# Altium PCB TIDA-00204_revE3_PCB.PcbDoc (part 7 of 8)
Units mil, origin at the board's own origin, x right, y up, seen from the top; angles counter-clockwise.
Board outline 4600 x 3740 mil, 8 copper layers (TopLayer - S1 (.GTL), MidLayer1 - S2 (.G1), MidLayer2 - S3 (.G2), MidLayer3 - S4 (.G3), MidLayer4 - S5 (.G4), MidLayer5 - S6 (.G5), MidLayer6 - S7 (.G6), BottomLayer - S8 (.GBL)), stack 58.938 mil thick; 536 components, 354 nets, 2015 pads, 1067 vias.
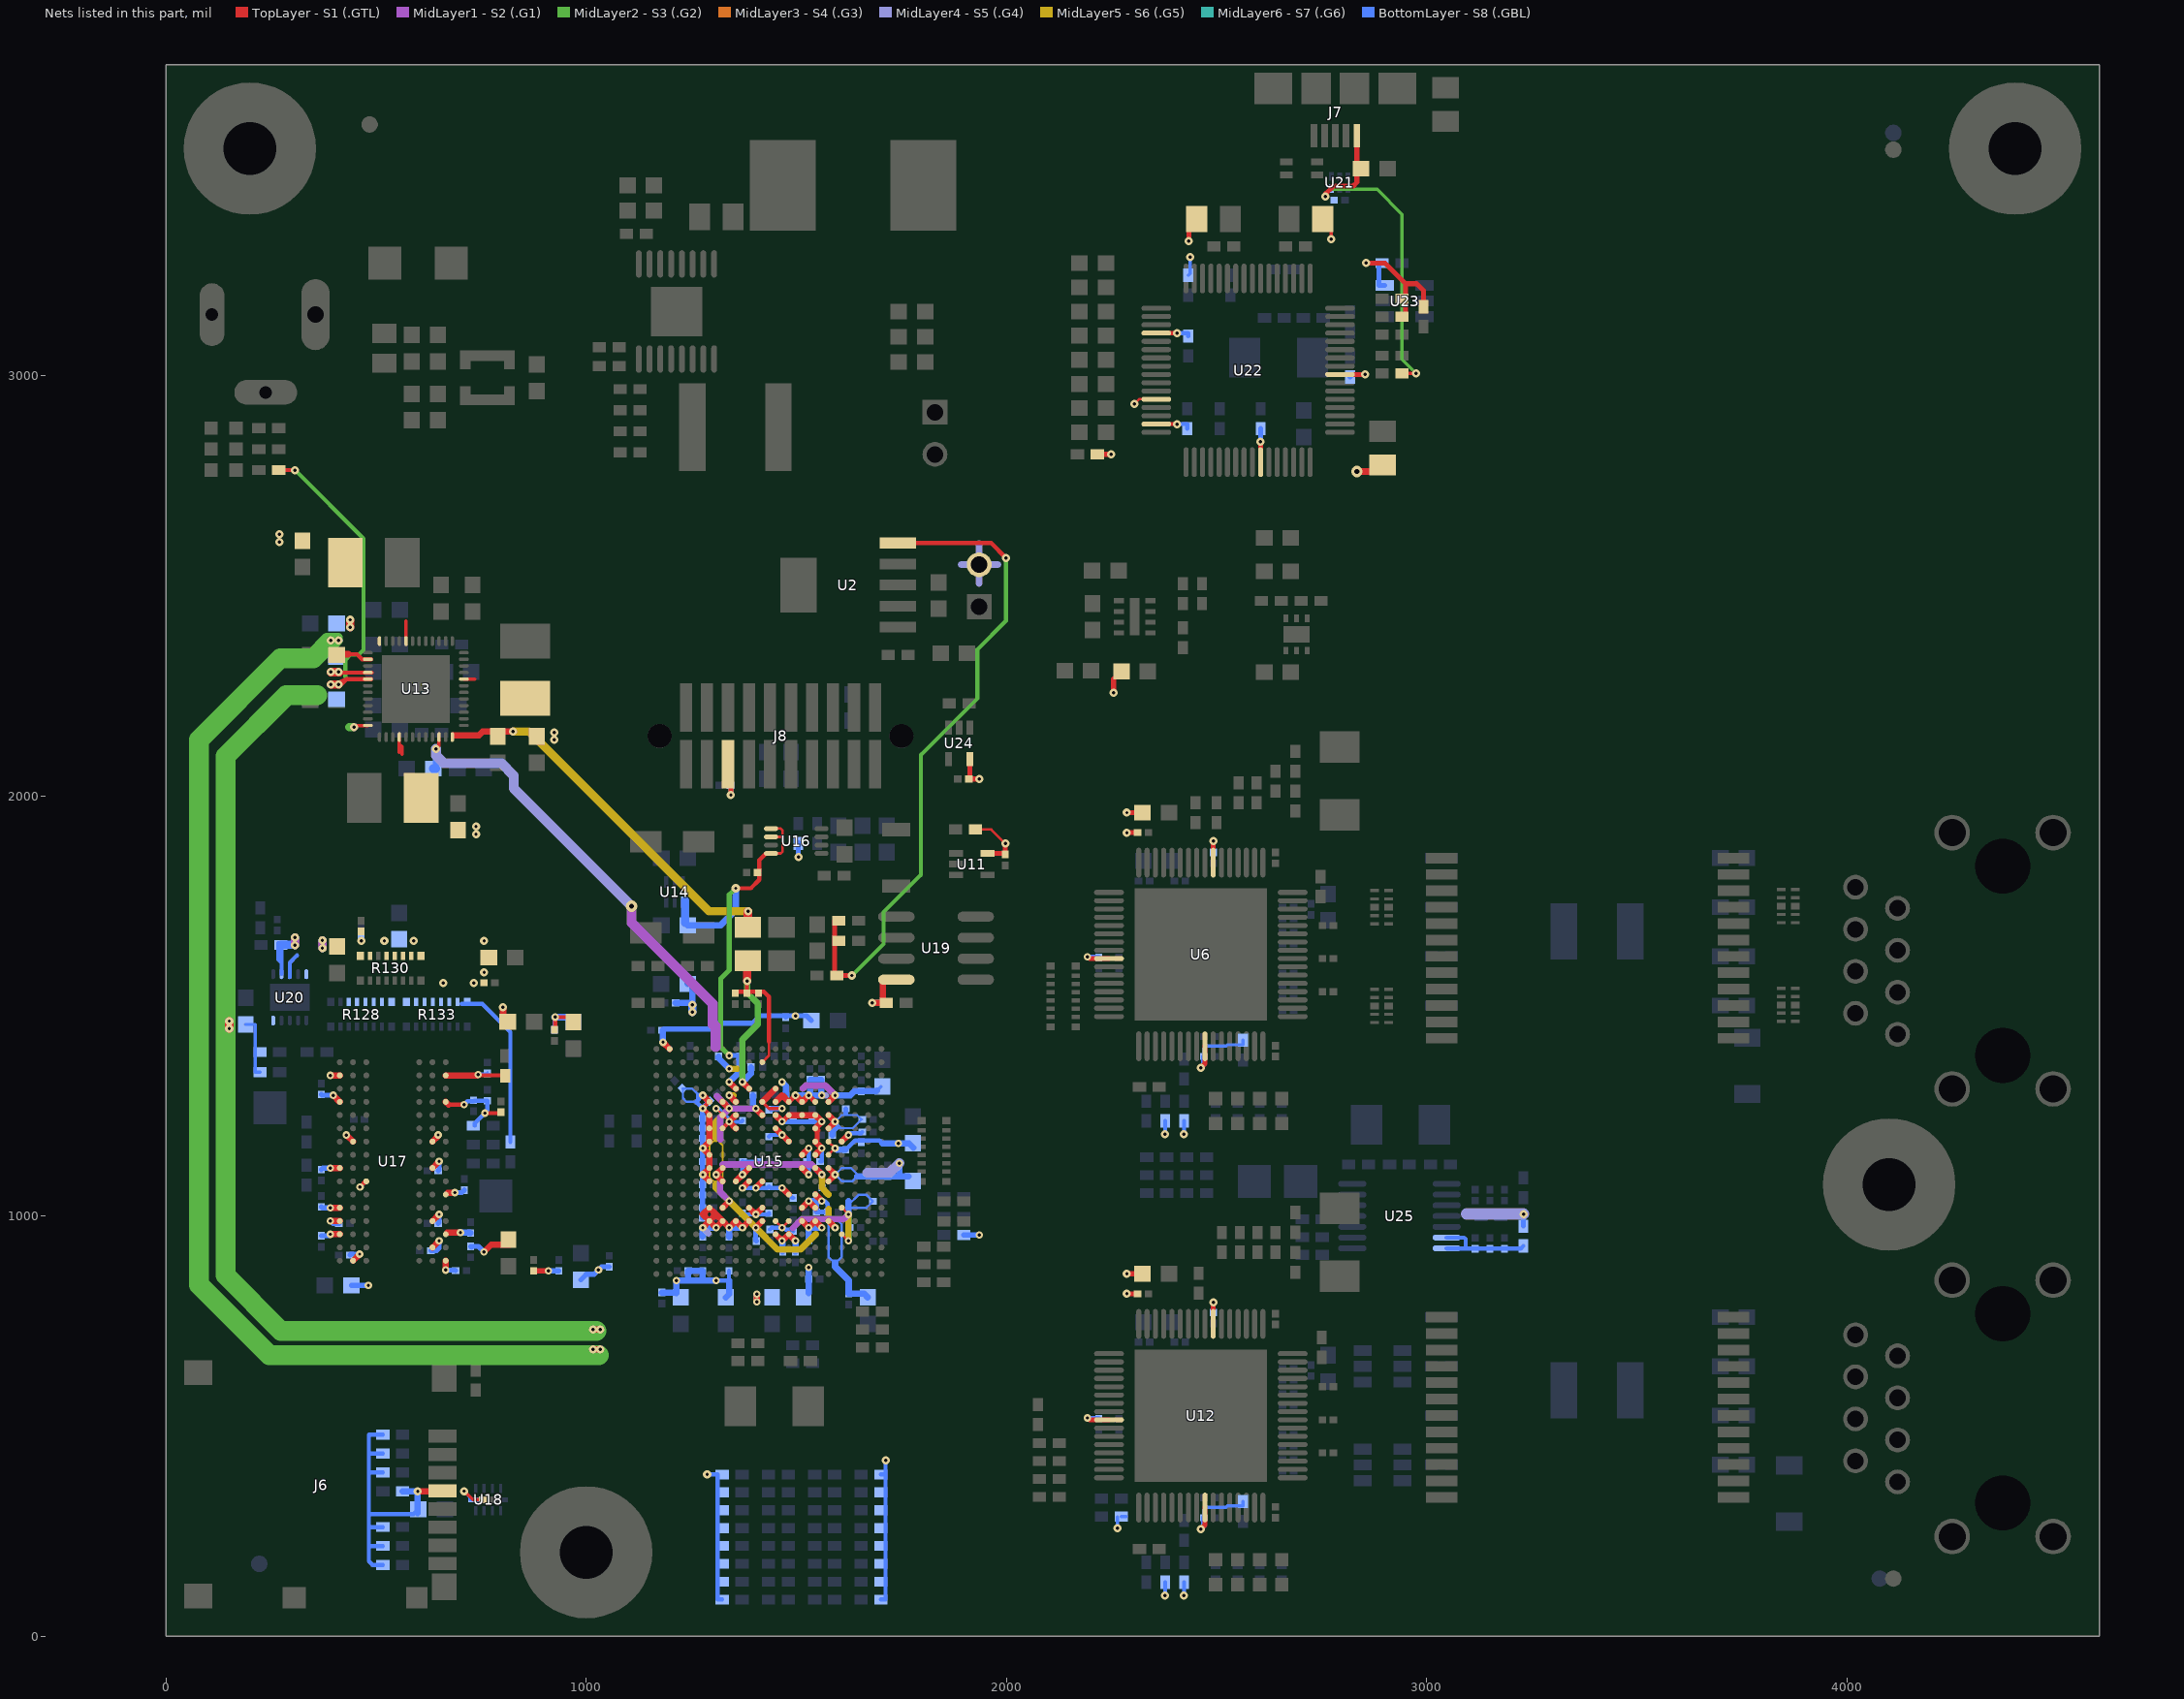
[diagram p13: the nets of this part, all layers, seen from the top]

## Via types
v1: diameter 19.68, hole 7.87, TopLayer - S1 (.GTL) to BottomLayer - S8 (.GBL), 600 vias
v2: diameter 17.72, hole 7.87, TopLayer - S1 (.GTL) to BottomLayer - S8 (.GBL), 408 vias
v3: diameter 27.56, hole 11.81, TopLayer - S1 (.GTL) to BottomLayer - S8 (.GBL), 31 vias
v4: diameter 20, hole 7.87, TopLayer - S1 (.GTL) to BottomLayer - S8 (.GBL), tented both sides, 11 vias
v5: diameter 15.75, hole 7.87, TopLayer - S1 (.GTL) to BottomLayer - S8 (.GBL), 9 vias
v6: diameter 20, hole 7.87, TopLayer - S1 (.GTL) to BottomLayer - S8 (.GBL), 5 vias
v7: diameter 15, hole 7.87, TopLayer - S1 (.GTL) to BottomLayer - S8 (.GBL), 2 vias
v8: diameter 18, hole 7.87, TopLayer - S1 (.GTL) to BottomLayer - S8 (.GBL), 1 vias

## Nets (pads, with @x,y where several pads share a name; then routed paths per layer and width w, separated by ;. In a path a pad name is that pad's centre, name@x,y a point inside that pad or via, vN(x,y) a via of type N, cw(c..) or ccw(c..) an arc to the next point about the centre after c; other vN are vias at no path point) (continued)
VAUX2: C96.1 C102.1 C103.1 C104.1 C108.1 C109.1 C110.1 C114.1 C115.1 C116.1 C117.2 C118.2 C119.2 C120.2 C121.2 C122.2 C123.2 C124.2 C125.2 C126.2 R70.2 R83.2 R84.2 R85.2 R86.2 R87.2 R88.2 R89.2 R90.2 R91.2 R92.2 R93.2 R94.2 R95.2 R96.2 R97.2 R98.2 R117.2 R118.2 U2.5 U13.48 U15.E10 U15.E11 U15.E12 U15.E13 U15.F14 U15.G14 U15.K14 U15.L14 U15.N5 U15.P5 U15.P6 U15.P7 U15.P8 U15.P12 U15.P13 | length 4215
  TopLayer - S1 (.GTL) w9.84: U2.5@1741.61,2601.5 1963.46,2601.5 v1(1999.02,2565.94)
  TopLayer - S1 (.GTL) w12: U15.E11@1482.24,1271.76 v2(1497.99,1287.48) ; v2(1529.49,1287.48) U15.E13@1545.24,1271.75 ; R118.2@1601.38,1702.5 1591.5,1702.5 1591.5,1572.5 R70.2@1596.12,1572.5 v1(1632.5,1572.5)
  TopLayer - S1 (.GTL) w15: v2(1277.52,972.52) U15.P5@1293.27,988.27 ; 1277.52,1004.04 U15.P5@1293.25,988.31 ; 1277.53,1004.04 U15.N5@1293.27,1019.76 1309.02,1004.03 ; U15.P5@1293.27,988.27 1309.02,1004.03 ; v2(1309.02,972.52) U15.P6@1324.76,988.27 1309.02,1004.03 ; v2@1309,972.56 U15.P5@1293.27,988.27 ; U15.P6@1324.76,988.27 v2(1340.51,972.52) U15.P7@1356.26,988.27 v2(1372.01,972.52) U15.P8@1387.76,988.27 ; U15.E10@1450.75,1271.73 1466.5,1287.49 ; 1466.54,1287.52 1466.5,1287.49 ; U15.E11@1482.24,1271.75 1466.5,1287.49 ; v2(1497.99,1287.48) U15.E12@1513.74,1271.78 ; U15.P12@1513.75,988.28 v2(1529.49,972.52) U15.P13@1545.24,988.27 ; U15.E12@1513.74,1271.75 v2(1529.49,1287.48) ; U15.P13@1545.24,988.27 v2(1560.98,972.52) ; U15.L14@1576.73,1082.76 v2(1592.48,1098.5) U15.K14@1576.73,1114.25 ; U15.G14@1576.73,1208.76 v2(1592.48,1224.49) ; U15.F14@1576.73,1240.24 v2(1592.48,1224.49)
  TopLayer - S1 (.GTL) w19.68: v1(438.98,2400.83) v1@438.98,2415.83
  MidLayer2 - S3 (.G2) w9.84: v1(1632.5,1572.5) 1707.68,1647.68 1707.68,1723.43 1796.26,1812.01 1796.26,2097.44 1931.1,2232.28 1931.1,2348.43 1999.02,2416.34 v1(1999.02,2565.94)
  MidLayer4 - S5 (.G4) w15: v2(1277.52,972.52) 1291.04,959 ; v2(1560.98,1287.48) 1571.52,1287.48
  MidLayer4 - S5 (.G4) w23.62: 1669.25,1103.35 1722.44,1103.35 v2(1745.08,1125.98)
  BottomLayer - S8 (.GBL) w5: 1592.48,1208.82 1592.66,1209 1607.97,1209 ; C121.2@1657.01,1230 C121.2@1655,1230 ; 1607.97,1209 1634,1209 C121.2@1655,1230 ; 1607.97,1209 v2(1592.48,1224.49) 1607.99,1240 1645,1240 C121.2@1655,1230
  BottomLayer - S8 (.GBL) w5.51: v2(1592.48,1098.5) 1608.15,1114.17 1630.32,1114.17 1649.98,1094.51 1651.66,1092.82 ; v2@1593.5,1098.43 1609.25,1082.68 1632.48,1082.68 1644.31,1094.51
  BottomLayer - S8 (.GBL) w6: C124.2@1529.49,1324.51 C124.2@1532.5,1324.51 ; v2(1560.98,1287.48) v2@1562.5,1287.48
  BottomLayer - S8 (.GBL) w10: v1(1288,385) 1312.5,385 1312.5,87.5 R98.2@1323.88,87.5 ; v2(1309.02,846.54) 1339.36,846.54 1339.43,846.47 1339.49,846.54 1340,847.05 C118.2@1340,869.51 ; R97.2@1701.12,87.5 1712.5,87.5 R83.2@1712.5,385 ; R83.2@1701.12,385 R83.2@1712.5,385 ; v1(1712.5,419) R83.2@1712.5,385
  BottomLayer - S8 (.GBL) w12: 1617.99,1243.49 C123.2@1617.99,1255
  BottomLayer - S8 (.GBL) w15: C119.2@1180,817.99 1213.5,817.99 1214.53,816.97 v2(1214.53,846.54) 1242.99,846.54 ; C117.2@1277.5,950.98 v2(1277.52,972.52) v2(1309.02,972.52) ; v2(1309.02,846.54) 1277.5,846.54 ; C104.1@1332.5,806.5 1340.51,814.51 1340.51,846.54 1339.49,846.54 1339.36,846.54 ; C102.1@1340,950.49 1340.51,951 v2(1340.51,972.52) v2(1372.01,972.52) ; v2(1497.99,1287.48) v2(1529.49,1287.48) v2@1532.5,1287.48 ; C110.1@1529.47,817.02 v2(1529.47,878.04) ; C108.1@1530,942.99 1530,972.01 v2(1529.49,972.52) v2(1560.98,972.52) ; v2(1560.98,1287.48) v2@1560,1287.48 ; C122.2@1585.49,1192.5 1585.49,1201.83 1592.48,1208.82 v2(1592.48,1224.49) ; 1644.31,1094.51 1649.98,1094.51 C114.1@1685,1094.51 C115.1@1717.5,1094.51 1745.08,1094.51 ; 1242.99,846.54 1277.5,846.54 ; 1242.99,846.54 C120.2@1242.99,870 1277.01,870 C103.1@1277.5,869.51 1277.5,846.54 ; v2@1532.5,1287.48 C124.2@1532.5,1324.51 C125.2@1560,1324.51 v2@1560,1287.48 ; v2@1532.5,1287.48 v2@1560,1287.48
  BottomLayer - S8 (.GBL) w15.75: v2(1745.08,1125.98) 1745.08,1094.51 C116.1@1767.17,1094.51
  other v1: 438.98,2418.83
VAUX33: C93.1 C136.1 C137.1 C233.1 R66.2 R135.2 R137.2 U13.4 U13.12 U15.N15 U15.R15 U20.10 | length 4020.4
  TopLayer - S1 (.GTL) w6: U15.R15@1608.23,956.77 v2(1623.98,941.02) ; U15.N15@1608.23,1019.76 v2(1623.98,1004.02)
  TopLayer - S1 (.GTL) w8: v1(448,2163) 452.39,2167.39 U13.12@480.83,2167.39
  TopLayer - S1 (.GTL) w9: v1@389,2291 391,2289 415.26,2289 v1@419.63,2293.37 ; v1@414,2299 v1@419.63,2293.37 ; v1@416.63,2293.37 v1@419.63,2293.37 ; U13.4@490,2293.37 U13.4@480.83,2293.37 v1@419.63,2293.37
  TopLayer - S1 (.GTL) w9.84: R66.2@268.62,2775 v1(307.5,2775)
  TopLayer - S1 (.GTL) w15.75: v1(1016,730) v1(1034,730)
  TopLayer - S1 (.GTL) w19.68: v1(151,1446) v1(151,1464) ; v1(393,2294.5) v1(411,2294.5)
  MidLayer1 - S2 (.G1) w15: 1491.25,971.25 1513.11,993.11 1613.07,993.11 v2(1623.98,1004.02)
  MidLayer1 - S2 (.G1) w19.68: v1(151,1446) v1(151,1464)
  MidLayer2 - S3 (.G2) w9.84: v1(307.5,2775) 470.47,2612.03 470.47,2347.44 458.66,2335.63 438.98,2335.63 427.17,2323.82 427.17,2282.48
  MidLayer2 - S3 (.G2) w19.68: 436.5,2163 v1(448,2163)
  MidLayer2 - S3 (.G2) w47.24: 360,2239 287,2239 142,2094 142,859 274,727 v1@1025,727
  MidLayer3 - S4 (.G3) w19.68: v1(151,1446) v1(151,1464)
  MidLayer4 - S5 (.G4) w19.68: v1(151,1446) v1(151,1464)
  MidLayer5 - S6 (.G5) w15: v2(1623.98,941.02) v2(1623.98,1004.02)
  MidLayer5 - S6 (.G5) w19.68: v1(151,1446) v1(151,1464)
  MidLayer6 - S7 (.G6) w19.68: v1(151,1446) v1(151,1464)
  BottomLayer - S8 (.GBL) w5: 1623.98,1020 1624.28,1019.7
  BottomLayer - S8 (.GBL) w5.51: 1622.83,1025.2 1623.98,1026.34 1648.74,1051.1 1665.91,1051.1 C136.1@1682.01,1035 1666.71,1019.7 1624.28,1019.7
  BottomLayer - S8 (.GBL) w8: C233.1@190,1456 213,1456 213,1342.5 R137.2@223.88,1342.5
  BottomLayer - S8 (.GBL) w15: v2(1623.98,941.02) v2(1623.98,1004.02) 1623.98,1020 1623.98,1026.34 1623.98,1035.28
VDAC: C98.1 C127.1 C128.1 C129.1 C130.1 C131.1 U13.22 U15.E6 U15.E14 U15.F9 U15.K13 U15.N6 U15.P9 U15.P14 | length 2843.4
  TopLayer - S1 (.GTL) w8: v1(643,2112) 650.12,2119.12 U13.22@650.12,2139.83
  TopLayer - S1 (.GTL) w15: U15.N6@1324.76,1019.76 v2(1340.51,1035.51) ; U15.E6@1324.76,1271.73 v2(1340.51,1255.98) ; v2(1403.5,972.52) U15.P9@1419.25,988.29 ; v2(1403.5,1255.98) U15.F9@1419.25,1240.26 ; U15.K13@1545.24,1114.25 v2(1560.98,1098.5) ; U15.P14@1576.73,988.27 v2(1592.48,972.52) ; U15.E14@1576.73,1271.75 v2(1592.48,1287.48)
  MidLayer1 - S2 (.G1) w15: 1318.9,1079.72 1318.9,1057.13 v2(1340.51,1035.51)
  MidLayer1 - S2 (.G1) w15.75: 1311.02,1285.47 v2(1340.51,1255.98) ; 1318.9,1182.09 1318.9,1234.37 v2(1340.51,1255.98) ; 1324.8,1123.03 1536.46,1123.03 v2(1560.98,1098.5) ; v2(1403.5,1255.98) v2(1340.51,1255.98) ; 1515.75,1304.13 1522.64,1311.02 1568.94,1311.02 v2(1592.48,1287.48)
  MidLayer1 - S2 (.G1) w23.62: v3(1108.27,1737.2) 1108.27,1697.73 1301.18,1504.82 1301.18,1454.72 ; 1308.07,1401.57 1308.07,1451.77
  MidLayer4 - S5 (.G4) w23.62: v1(643,2112) 643,2096.17 661.42,2077.76 798.23,2077.76 827.76,2048.23 827.76,2017.72 v3(1108.27,1737.2)
  MidLayer5 - S6 (.G5) w4.72: 1293.31,1092.48 1293.31,1168.35 1309.02,1184.06 1324.8,1168.27 1324.8,1092.56 1309.02,1076.77 1293.31,1092.48
  MidLayer5 - S6 (.G5) w15: 1576.77,1016.73 1576.77,988.23 v2(1592.48,972.52)
  MidLayer5 - S6 (.G5) w15.75: 1309.02,1076.77 1309.02,1067.01 v2(1340.51,1035.51) v2(1403.5,972.52) 1455.75,920.28 1509.84,920.28 1546.26,956.69 ; 1309.02,1184.06 1309.02,1224.49 v2(1340.51,1255.98) ; v2(1560.98,1098.5) 1560.98,1066.97 1576.77,1051.18
  BottomLayer - S8 (.GBL) w6: C129.1@1560.98,1068.71 v2(1560.98,1098.5)
  BottomLayer - S8 (.GBL) w8: C131.1@1691.88,1298.38 C131.1@1701,1307.5
  BottomLayer - S8 (.GBL) w12: v2(1403.5,972.52) 1403.5,941.99 C130.1@1405,940.49
  BottomLayer - S8 (.GBL) w15: C98.1@643,2065 v1(643,2112) ; C127.1@1397.01,1287.5 1397.01,1262.48 v2(1403.5,1255.98) ; v2(1592.48,1287.48) 1628.62,1287.48 1638.15,1297.01 C128.1@1655,1297.01 1690.51,1297.01 C131.1@1691.88,1298.38
  BottomLayer - S8 (.GBL) w20: C98.1@636.5,2065 C98.1@643,2065
VDC_USB: C234.1 C235.1 J7.1 R155.2 U21.6 | length 831.5
  TopLayer - S1 (.GTL) w7.87: R155.2@2941.12,3005 v1(2974.41,3005)
  TopLayer - S1 (.GTL) w11.81: v1@2759.84,3433.07 2777.56,3450.79 2824.8,3450.79 2833.68,3459.67 J7.1@2833.68,3570.71
  MidLayer2 - S3 (.G2) w7.87: v1@2759.84,3433.07 2769.68,3442.91 2881.89,3442.91 2940.94,3383.86 2940.94,3038.46 v1(2974.41,3005)
  other v1: 2758.86,3426.18
VDD1_SMPS: C86.1 C185.1 C186.1 C187.1 C188.1 C189.1 C190.1 L3.2 U13.32 U15.A2 U15.F10 U15.F11 U15.F12 U15.F13 U15.G13 U15.H13 U15.J13 | length 818.1
  TopLayer - S1 (.GTL) w8: U13.32@709.17,2277.62 734.62,2277.62
  TopLayer - S1 (.GTL) w12: v2(1466.5,1224.49) U15.F11@1482.23,1240.26 ; U15.H13@1545.24,1177.26 1550,1182.02 U15.G13@1550,1204
  TopLayer - S1 (.GTL) w15: v2(1183.03,1413.46) U15.A2@1198.78,1397.72 ; U15.F10@1450.76,1240.25 v2(1466.5,1224.49) ; U15.F11@1482.23,1240.26 1545.24,1240.26 v2(1560.98,1224.49) 1545.24,1208.76 U15.G13@1550,1204 ; U15.J13@1545.24,1145.77 v2(1560.98,1161.5) U15.H13@1545.25,1177.25
  BottomLayer - S8 (.GBL) w9.84: C190.1@1557.01,1130 1560.98,1130 v2(1560.98,1161.5)
  BottomLayer - S8 (.GBL) w11.81: v2(1466.5,1224.49) v2(1560.98,1224.49)
  BottomLayer - S8 (.GBL) w12: C187.1@1180.49,1442.5 1183.03,1442.5 1185.41,1444.88 1302.38,1444.88 1316.16,1458.66 1395.67,1458.66 1413.46,1476.46 C186.1@1478.46,1476.46 ; C186.1@1475,1472.99 C186.1@1478.46,1476.46 ; C185.1@1536,1465 1524.55,1476.46 v2(1497.99,1476.46) C186.1@1478.46,1476.46
  BottomLayer - S8 (.GBL) w15: v2(1183.03,1413.46) C187.1@1183.03,1442.5
  other v1: 924,2133 924,2151
VDD2_SMPS: C88.1 C170.1 C171.1 C172.1 C173.1 C174.1 C175.1 C176.1 C177.1 C178.1 C179.1 C180.1 C181.1 C182.1 C183.1 C184.1 L4.2 U13.44 U15.F6 U15.F7 U15.G6 U15.G7 U15.G10 U15.H11 U15.J12 U15.K6 U15.K8 U15.K12 U15.L6 U15.L7 U15.L8 U15.L9 U15.M11 U15.M13 U15.N8 U15.N9 U15.N12 U15.N13 | length 1613.3
  TopLayer - S1 (.GTL) w4: U15.F6@1324.76,1240.26 U15.F6@1324.76,1241.24
  TopLayer - S1 (.GTL) w5: v2@1309,1257 U15.F6@1324.76,1241.24 ; U15.F6@1324.76,1240.26 v2(1340.51,1224.49)
  TopLayer - S1 (.GTL) w8: U13.44@571.38,2368.17 571.38,2416.12
  TopLayer - S1 (.GTL) w10: U15.G6@1324.76,1208.78 v2(1340.51,1224.49)
  TopLayer - S1 (.GTL) w15: U15.L6@1324.76,1082.76 v2(1309.02,1098.5) U15.K6@1324.75,1114.27 ; U15.L7@1356.26,1082.76 v2(1372.01,1098.5) ; U15.G7@1356.26,1208.76 v2(1340.51,1224.49) U15.F7@1356.24,1240.25 ; v2(1372.01,1067.01) U15.L8@1387.76,1082.76 ; v2(1372.01,1098.5) U15.K8@1387.75,1114.26 ; U15.N8@1387.76,1019.76 v2(1403.5,1004.02) U15.N9@1419.25,1019.78 ; v2(1403.5,1067.01) U15.L9@1419.25,1082.78 ; U15.G10@1450.75,1208.75 U15.H11@1482.24,1177.26 ; v2(1466.5,1067.01) U15.M11@1482.24,1051.26 ; U15.N12@1513.74,1019.76 v2(1529.49,1035.51) ; U15.K12@1513.74,1114.25 v2(1529.49,1098.5) ; U15.J12@1513.74,1145.77 v2(1529.49,1161.5) ; v2(1529.49,1035.51) U15.N13@1545.24,1019.76 ; U15.M13@1545.24,1051.26 v2(1560.98,1035.51)
  BottomLayer - S8 (.GBL) w4.92: 1606.69,865.75 1608.27,867.32
  BottomLayer - S8 (.GBL) w5.51: 1588.88,883.56 1592.72,887.4 1608.07,902.76 1608.07,980.31 1598.03,990.35 1576.57,990.35 1576.57,902.76 1585.63,893.7 1597.83,893.7
  BottomLayer - S8 (.GBL) w7.87: C184.1@1372.01,1129.02 C184.1@1372.99,1130 C181.1@1409.51,1130
  BottomLayer - S8 (.GBL) w9.84: v2(1309.02,1255.98) 1313.9,1255.98 1340.51,1229.37 v2(1340.51,1224.49) 1369.23,1224.49 C182.1@1372,1227.26 ; C175.1@1372,1006.76 1372,1004.02 v2(1403.5,1004.02) 1435,1004.02 C180.1@1435,1007.01 ; v2(1372.01,1067.01) v2(1403.5,1067.01) 1431,1067.01 C183.1@1435,1071.01 1439,1067.01 v2(1466.5,1067.01) 1490.51,1042.99 C172.1@1492.5,1042.99 ; C176.1@1435,1188.99 1439,1192.99 v2(1466.5,1192.99) ; v2(1529.49,1098.5) v2(1529.49,1161.5) ; v2(1560.98,1035.51) 1567.83,1035.51 1574.51,1028.84 C173.1@1574.51,1010
  BottomLayer - S8 (.GBL) w11.81: v2(1372.01,1098.5) C184.1@1372.01,1129.02 ; 1547.99,1036.65 1547.99,1035.51 C174.1@1547.99,1010 C173.1@1574.51,1010 1576.57,1007.93 1576.57,990.35
  BottomLayer - S8 (.GBL) w15: v2(1529.49,1035.51) 1547.99,1035.51 v2(1560.98,1035.51)
  BottomLayer - S8 (.GBL) w15.75: C179.1@1212.99,1507.5 v1@1252.95,1507.5 ; C171.1@1241.5,1552.5 1252.95,1552.5 v1@1252.95,1507.5 ; v1(1252.95,1502.95) v1@1252.95,1507.5 ; 1592.72,888.39 1592.72,887.4 1592.72,879.72 1606.69,865.75 1625,847.44 C178.1@1625,815.49 1661,815.49 C170.1@1670,806.5
  BottomLayer - S8 (.GBL) w19.68: v1(1252.95,1484.95) v1(1252.95,1502.95)
  other v1: 270,2604 270,2622
VDDA_ADC: C144.1 C195.1 C196.1 C197.1 L6.1 U15.B9 U15.D8 | length 647.8
  TopLayer - S1 (.GTL) w6.3: U15.B9@1419.25,1366.24 1435,1381.99 1435,1415.02
  TopLayer - S1 (.GTL) w10: C195.1@1355,1530.49 1358.51,1534 C196.1@1382.5,1534 ; C196.1@1382.5,1530.49 C196.1@1382.5,1534 ; v1(1383,1559) 1382.5,1558.5 C196.1@1382.5,1534 ; 1435,1415.02 1435,1522 1423,1534 C196.1@1382.5,1534
  TopLayer - S1 (.GTL) w15: v2(1372.01,1318.98) U15.D8@1387.76,1303.25
  TopLayer - S1 (.GTL) w20: v1(1383,1559) L6.1@1383,1597
  MidLayer2 - S3 (.G2) w15: v2(1372.01,1318.98) 1372.01,1420.01 1409,1457 1409,1505.5 1383,1531.5 v1(1383,1559)
  BottomLayer - S8 (.GBL) w15: v2(1372.01,1318.98) 1392.5,1339.47 C144.1@1392.5,1354.51
VDDIO: C35.1 C40.1 C41.1 C42.1 C43.1 C44.1 C67.1 C68.1 C69.1 C70.1 C71.1 C207.2 C238.2 C239.2 C243.2 C244.2 C245.2 C246.2 C247.2 J3.2 J8.5 L9.1 L11.1 L12.1 L14.1 R12.1 R28.1 R29.1 R30.2 R38.2 R49.2 R55.1 R56.1 R59.2 R76.2 R146.2 R148.2 R149.2 R150.2 R152.2 R156.2 U6.23 U6.41 U6.57 U11.5 U12.23 U12.41 U12.57 U19.8 U22.20 U22.28 U22.31 U22.42 U22.56 U23.6 U24.5 | length 3010.1
  TopLayer - S1 (.GTL) w5.91: R38.2@1926.12,1920 1963.78,1920 v1(1997.5,1886.28) ; v1(2304.13,2932.09) 2315.65,2943.6 U22.28@2356.5,2943.6
  TopLayer - S1 (.GTL) w7.87: L9.1@2752.5,3372.5 2772.64,3352.36 v1(2772.64,3324.8)
  TopLayer - S1 (.GTL) w9.84: U22.31@2356.5,2884.55 v1(2405.51,2884.55) ; U22.20@2356.5,3101.08 v1(2405.51,3101.08)
  TopLayer - S1 (.GTL) w11.81: v1(1344.39,2002.26) J8.5@1344.39,2075 ; C243.2@1910.49,2040 C243.2@1913.09,2040 ; U24.5@1913.09,2087.6 C243.2@1913.09,2040 ; v1(1935.04,2040) C243.2@1913.09,2040 ; U11.5@1954.9,1863.09 1994.9,1863.09 C35.1@1997.5,1860.49 v1(1997.5,1886.28) ; R146.2@2216.12,2812.5 v1(2249.02,2812.5) ; v1(2434.06,3319.88) 2434.06,3354.06 L11.1@2452.5,3372.5 ; U22.42@2604.53,2794 v1(2604.53,2842.72) ; U22.56@2793.5,3002.66 v1(2853.64,3002.66) ; v1(2855.32,3267.72) 2900.59,3267.72 2949.8,3218.5 ; R149.2@2941.12,3140 2949.8,3140 2949.8,3218.5 ; R150.2@2992.5,3163.62 2992.5,3202.38 2976.38,3218.5 2949.8,3218.5
  TopLayer - S1 (.GTL) w12: v2@2197.44,515.16 U12.41@2244,515.16 ; v2@2197.44,1612.66 U6.41@2244,1612.66 ; v1(2255,2245) 2255,2277.5 R12.1@2273.5,2296 ; v1(2286.5,815) C68.1@2312.01,815 ; v1(2286.5,862.5) C67.1@2323.5,862.5 ; v1(2286.5,1912.5) C41.1@2312.01,1912.5 ; v1(2286.5,1960) C40.1@2323.5,1960 ; v1(2462.5,255) 2472.34,264.84 U12.57@2472.34,306.5 ; v1(2462.5,1352.5) 2472.34,1362.34 U6.57@2472.34,1404 ; U12.23@2492.03,743.5 v1(2492,795) ; U6.23@2492.03,1841 v1(2492,1892.5)
  TopLayer - S1 (.GTL) w15: v1(1680.5,1507.5) 1705.5,1507.5 1705.5,1562.5 U19.8@1738.01,1562.5
  TopLayer - S1 (.GTL) w15.75: v3(2833.66,2771.65) 2895,2771.65 L12.1@2895,2787.5
  MidLayer4 - S5 (.G4) w15.75: v1(1680.5,1507.5) 1715.18,1507.5 ; 1892.52,2550 J3.2@1935,2550 ; 1935,2504.96 J3.2@1935,2550 ; 1935,2600.35 J3.2@1935,2550 ; 1979.53,2550 J3.2@1935,2550
  MidLayer4 - S5 (.G4) w27.56: 3095,1005 v1(3230,1005)
  BottomLayer - S8 (.GBL) w7.87: v1(2263.78,257.45) R49.2@2263.78,284.45 ; R49.2@2273.62,285 R49.2@2284.45,285 ; R156.2@2432.5,3238.62 2437.01,3243.13 v1(2437.01,3281.5) ; C71.1@2469.51,282.5 2469.51,300.16 2476.38,307.03 2522.64,307.03 2525.59,309.98 2562.5,309.98 R55.1@2562.5,321.12 ; C44.1@2469.51,1380 2469.51,1397.66 2476.38,1404.53 2522.64,1404.53 2525.59,1407.48 2562.5,1407.48 R29.1@2562.5,1418.62
  BottomLayer - S8 (.GBL) w9.84: v1(2405.51,2884.55) 2430,2884.55 C245.2@2430,2873.88 ; v1(2405.51,3101.08) 2432.5,3101.08 C244.2@2432.5,3093.62
  BottomLayer - S8 (.GBL) w10: v1(2377.5,97) R56.1@2377.5,128.88 ; v1(2377.5,1194.5) R28.1@2377.5,1226.38 ; v1(2422.5,97) R59.2@2422.5,128.88 ; v1(2422.5,1194.5) R30.2@2422.5,1226.38
  BottomLayer - S8 (.GBL) w11.81: C238.2@1342.99,2025 1344.39,2023.6 v1(1344.39,2002.26) ; v1(1504.92,1854.33) 1504.92,1888.8 R152.2@1505,1888.88 ; R76.2@1898.62,955 v2(1935.5,955) ; v1(2604.53,2842.72) 2604.53,2873.88 C246.2@2605,2873.88 ; C247.2@2817.5,2996.38 2823.78,3002.66 v1(2853.64,3002.66) ; v1(2855.32,3267.72) 2885.83,3267.72 2885.83,3214.9 U23.6@2900.26,3214.9 ; L14.1@3230,976.12 v1(3230,1005)
  BottomLayer - S8 (.GBL) w12: v2@2199.51,517.99 C70.1@2220,517.99 ; v2@2199.51,1615.49 C43.1@2220,1615.49 ; v1(2462.5,255) 2469.51,262.01 C71.1@2469.51,282.5 ; v1(2462.5,1352.5) 2469.51,1359.51 C44.1@2469.51,1380 ; C69.1@2492,770.36 v1(2492,795) ; C42.1@2492,1867.86 v1(2492,1892.5)
  other v2: 2192.91,519.68 2192.91,1617.18
VDDIO_CDC: C255.1 C256.1 C257.1 L14.2 U25.6 U25.7 | length 255.1
  BottomLayer - S8 (.GBL) w9.84: U25.7@3047.2,923.23 3047.93,922.5 3092.5,922.5 ; U25.6@3047.2,948.82 3088.68,948.82 3092.5,945 3092.5,922.5 ; L14.2@3230,928.88 3223.62,922.5 3092.5,922.5
VDDS_DDR: C90.1 C148.1 C149.1 C150.1 C151.1 C152.1 C153.1 C154.1 C155.1 C156.1 C157.1 C158.1 C159.1 C160.1 C161.1 C162.1 C163.1 C164.1 C165.1 C166.1 C167.1 C168.1 C169.1 C204.2 C211.1 C212.1 C213.1 C214.1 C215.1 C216.1 C217.1 C218.1 C219.1 C220.1 C221.1 C222.1 C223.1 C224.1 C231.1 C232.1 L5.2 R129.2 R136.2 U13.16 U15.E5 U15.F5 U15.G5 U15.H5 U15.J5 U15.K5 U15.L5 U17.A1 U17.A8 U17.B2 U17.C1 U17.C9 U17.D2 U17.D9 U17.E9 U17.F1 U17.G7 U17.H2 U17.H9 U17.K2 U17.K8 U17.N1 U17.N9 U17.R1 U17.R9 U20.2 | length 2656.4
  TopLayer - S1 (.GTL) w8: 555.63,2103.37 555.63,2123.37 ; U13.16@555.63,2139.83 555.63,2123.37 ; 562,2099 562,2117 555.63,2123.37
  TopLayer - S1 (.GTL) w9.84: v2@740.99,1334.72 806.66,1334.72 R129.2@807.5,1333.88
  TopLayer - S1 (.GTL) w10: v2@462.48,1069.48 475.76,1082.76 U17.G7@477.01,1082.76 ; v2@648,1190.75 v2(648,1193) ; U17.C1@665.98,956.77 U17.C1@669.88,960.67 ; U17.F1@665.98,1051.26 U17.F1@670.57,1055.85 ; 672.75,1264.96 v2(709.73,1264.96) ; v2(759.39,1245) 795.49,1245 C166.1@797.5,1247.01 ; C168.1@925,1442.99 926.18,1442.99 v2(926.18,1473.43) 957.5,1473.43 C232.1@957.5,1461.5 ; U15.E5@1292.25,1271.75 1277.5,1257 U15.F5@1293.27,1241.23
  TopLayer - S1 (.GTL) w12: C161.1@875,869.51 v2(910.01,869.51)
  TopLayer - S1 (.GTL) w15: v2(391.76,956.77) U17.C9@414.02,956.77 ; v2(391.76,988.27) U17.D9@414.02,988.27 ; v2(391.76,1019.76) U17.E9@414.02,1019.76 ; v2(391.76,1114.25) U17.H9@414.02,1114.25 ; v2(391.76,1334.72) U17.R9@414.02,1334.72 ; v2(398.28,1287.47) U17.N9@414.02,1271.73 ; v2(429.76,1192.99) U17.K8@445.51,1177.24 ; U17.A8@445.51,893.78 v2(461.26,909.53) ; v2(462.19,1069.48) v2@462.48,1069.48 ; U17.B2@634.49,925.28 v2(650.24,941.03) ; U17.D2@634.49,988.27 v2(650.24,1004.02) ; U17.H2@634.49,1114.25 v2(650.24,1130) ; U17.K2@634.49,1177.24 v2@648,1190.75 ; v2(665.98,871.51) U17.A1@665.98,893.78 ; U17.N1@665.98,1271.73 672.75,1264.96 ; U17.R1@665.98,1334.72 v2@740.99,1334.72 ; U17.C1@669.88,960.67 v2(701.04,960.67) ; U17.F1@670.57,1055.85 v2(687.57,1055.85) ; v2(756.9,914.9) 774,932 C231.1@818.5,932 ; v2(1277.52,1098.5) U15.L5@1293.27,1082.76 ; v2(1277.52,1098.5) U15.K5@1293.27,1114.25 ; v2(1277.52,1287.48) 1293.27,1271.75 U15.E5@1292.25,1271.75 ; U15.K5@1293.27,1114.25 1293.26,1145.78 v2(1277.52,1161.5) 1293.26,1177.25 U15.F5@1293.27,1241.23
  TopLayer - S1 (.GTL) w15.75: v1(802.17,1497.05) 802.17,1462.5 C211.1@813.5,1462.5
  MidLayer1 - S2 (.G1) w19.68: v1(307,1645) v1(307,1663)
  MidLayer2 - S3 (.G2) w19.68: v1(307,1645) v1(307,1663)
  MidLayer3 - S4 (.G3) w19.68: v1(307,1645) v1(307,1663)
  MidLayer5 - S6 (.G5) w19.68: v1(307,1645) v1(307,1663)
  MidLayer6 - S7 (.G6) w19.68: v1(307,1645) v1(307,1663)
  BottomLayer - S8 (.GBL) w5: C165.1@759.42,1336.67 C165.1@765.47,1342.72 ; C158.1@1229.19,1303.31 C158.1@1230.32,1302.18 ; 1262.04,1271.46 1262.04,1271.85 ; v2@1274.06,1290.94 v2(1277.52,1287.48)
  BottomLayer - S8 (.GBL) w5.51: C158.1@1229.19,1303.31 1252.2,1303.31 1264.57,1290.94 ; C158.1@1230.32,1302.18 1230.32,1280.51 1238.98,1271.85 1262.04,1271.85 ; 1264.57,1275.98 1264.57,1286.22 ; v2@1274.06,1290.94 1264.57,1290.94 ; v2(1277.52,1287.48) 1276.26,1286.22 1264.57,1286.22 ; 1264.57,1286.22 1264.57,1290.94
  BottomLayer - S8 (.GBL) w8: R136.2@275.31,1643.31 R136.2@273.62,1645 v1(307,1645) v1@307,1645.58
  BottomLayer - S8 (.GBL) w9.06: R136.2@267.72,1649.61 267.72,1610.24 275.31,1602.64 ; U20.2@275.31,1575.62 275.31,1602.64 ; R136.2@275.31,1643.31 275.31,1602.64
  BottomLayer - S8 (.GBL) w9.84: 1262.04,1271.46 v2(1277.52,1255.98) ; 1262.04,1272 v2@1276.26,1286.22
  BottomLayer - S8 (.GBL) w10: v2(709.73,1264.96) 717.77,1273 732.25,1273 733.76,1274.51 C160.1@765,1274.51 765,1250.61 v2(759.39,1245) 735,1220.61 C204.2@735,1215 ; v2(742.94,1336.67) C165.1@759.42,1336.67 ; C162.1@925,1442.99 v2@925,1473.43
  BottomLayer - S8 (.GBL) w12: C215.1@370,952.99 387.98,952.99 v2(391.76,956.77) ; C217.1@370,1022.01 372.25,1019.76 v2(391.76,1019.76) ; C224.1@370,1110.49 373.76,1114.25 v2(391.76,1114.25) ; C216.1@370,1289.51 372.04,1287.47 v2(398.28,1287.47) ; v2(391.76,988.27) 397.53,982.5 C222.1@412.01,982.5 ; C223.1@437.99,907.5 440.02,909.53 v2(461.26,909.53) ; C212.1@441.5,835 v2(482,835) ; C219.1@630.49,917.5 643.9,917.5 650.24,923.84 v2(650.24,941.03) ; C213.1@647.99,982.5 650.24,984.75 v2(650.24,1004.02) ; C220.1@647.99,1107.5 650.24,1109.75 v2(650.24,1130) ; v2(665.98,871.51) 688,871.51 C218.1@689.51,870 ; v2(687.57,1055.85) 703.84,1055.85 C221.1@710,1062.01 ; C164.1@727.69,925.3 C164.1@725,927.99 743.81,927.99 v2(756.9,914.9) ; v2(910.01,869.51) C167.1@935,869.51 ; C148.1@987.5,848.5 1000.5,861.5 1019,861.5 v2(1029.5,872) 1037.01,879.51 C163.1@1055,879.51 ; C153.1@1277.01,995 C154.1@1277.01,1020 C152.1@1277.01,1050 C150.1@1277.01,1075 C151.1@1277.01,1130 C157.1@1277.01,1185 C159.1@1277.01,1209 C155.1@1277.01,1232.5 1277.01,1255.47 v2(1277.52,1255.98) 1277.52,1257.52 C156.1@1293.31,1273.31 1291.69,1273.31 v2(1277.52,1287.48)
  BottomLayer - S8 (.GBL) w15: v2(701.04,960.67) 723.84,960.67 C214.1@725,959.51
  BottomLayer - S8 (.GBL) w15.75: v2@925,1473.43 v2(926.18,1473.43) 970,1473.43 C149.1@970,1461.5
  BottomLayer - S8 (.GBL) w19.68: R136.2@273.62,1645 274.2,1645.58 307,1645.58 v1(307,1663)
  other v1: 738,1909 738,1927
VDIG2: C92.1 C132.1 C133.1 C138.1 C142.1 C143.1 C147.1 U13.5 U15.D10 U15.E7 U15.E9 U15.H15 U15.R10 U15.R11 | length 553.3
  TopLayer - S1 (.GTL) w4: v2@1466.23,1255.75 v2(1466.5,1255.98)
  TopLayer - S1 (.GTL) w7.5: U15.R10@1450.75,956.3 U15.R10@1450.75,956.77
  TopLayer - S1 (.GTL) w8: U15.E9@1419.25,1271.75 1435.25,1255.75 v2@1466.23,1255.75
  TopLayer - S1 (.GTL) w10: v1@410,2269 430.12,2277.62 ; v1@413,2260.5 430.12,2277.62 ; U13.5@489,2277.62 U13.5@480.83,2277.62 430.12,2277.62
  TopLayer - S1 (.GTL) w15: v2(1340.51,1287.48) U15.E7@1356.26,1271.75 ; U15.E9@1419.25,1271.75 U15.D10@1450.75,1303.25 ; U15.R10@1450.75,956.3 1451.22,956.3 v2(1466.5,941.02) U15.R11@1482.24,956.77 ; U15.R11@1482.71,956.3 v2(1497.99,941.02) ; U15.H15@1608.23,1177.26 v2(1623.98,1192.99)
  TopLayer - S1 (.GTL) w19.68: v1(393,2265) v1(411,2265)
  MidLayer5 - S6 (.G5) w15: v2(1340.51,1287.48) 1351.3,1287.48 ; v2(1340.51,1350.47) 1360.31,1350.47
  BottomLayer - S8 (.GBL) w10: v2(1623.98,1192.99) 1627.98,1197 1654.01,1197 C133.1@1657.01,1200
  BottomLayer - S8 (.GBL) w12: C138.1@1440,1252.99 1442.99,1255.98 v2(1466.5,1255.98)
  BottomLayer - S8 (.GBL) w15: C142.1@1315,1379.51 1315,1375.98 v2(1340.51,1350.47) ; v2(1466.5,941.02) 1467.5,940.02 C143.1@1467.5,915.49 ; v2(1466.5,1318.98) 1475.49,1309.98 C132.1@1475.49,1287.5 ; C147.1@1497.5,915.49 1497.99,915.98 v2(1497.99,941.02)
VMMC: C94.1 C105.2 C106.2 C107.2 C111.2 C112.2 C113.2 C202.1 C203.2 C205.1 J6.4 R120.2 R121.2 R122.2 R123.2 R124.2 R125.2 U13.2 U15.H14 U15.J14 U15.P10 U15.P11 U18.10 | length 4348.5
  TopLayer - S1 (.GTL) w6: U15.P10@1450.76,988.28 v2(1466.5,972.52) U15.P11@1482.24,988.27 ; U15.J14@1576.73,1145.77 v2(1592.48,1161.5) ; U15.H14@1576.74,1177.25 v2(1592.48,1161.5)
  TopLayer - S1 (.GTL) w8: v1(709.65,345.47) 730.12,325 C205.1@754.29,325
  TopLayer - S1 (.GTL) w10: 435,2337 455,2337 467.13,2324.87 U13.2@480.83,2324.87 U13.2@488,2324.87
  TopLayer - S1 (.GTL) w15: v1(599.5,345) 657.32,345 J6.4@658.56,346.24
  TopLayer - S1 (.GTL) w15.75: C94.1@416.5,2337 435,2337 ; v1(1016,683) v1(1034,683) ; v2(1406,796) v2(1406,814)
  MidLayer2 - S3 (.G2) w19.68: 341,2337 382,2378 411,2378 v1(411,2370) ; v1(411,2370) 411,2368 375,2332 375,2351 375,2370 v1(393,2370) v1(411,2370)
  MidLayer2 - S3 (.G2) w47.24: 380,2356 375,2351 351,2327 273,2327 79.5,2133.5 79.5,836.5 246.5,669.5 1030.5,669.5
  MidLayer3 - S4 (.G3) w15.75: v2(1406,796) v2(1406,814)
  MidLayer4 - S5 (.G4) w15.75: v2(1406,796) v2(1406,814)
  MidLayer5 - S6 (.G5) w15.75: v2(1406,796) v2(1406,814)
  MidLayer6 - S7 (.G6) w15.75: v2(1406,796) v2(1406,814)
  BottomLayer - S8 (.GBL) w8: v1(709.65,345.47) 723.82,331.3 723.82,325 U18.10@731.85,325
  BottomLayer - S8 (.GBL) w9.84: C106.2@1437.5,967.99 1441.56,972.05 1470.67,972.05 1475.19,967.53 1489.48,967.53 C105.2@1492.5,964.51
  BottomLayer - S8 (.GBL) w10: R125.2@516.38,170 492,170 483,179 483,215 ; R124.2@516.38,215 483,215 ; R123.2@516.38,260 483,260 ; R122.2@516.38,390 483,390 ; R121.2@516.38,435 483,435 ; R120.2@516.38,480 484,480 483,479 483,435 ; C202.1@600.79,302.5 599.5,301.21 589.29,291 483,291 ; C111.2@1617.5,1157.99 1617.99,1157.99 1640,1180 1698,1180 1705.01,1172.99 ; 483,215 483,260 ; 483,260 483,291 ; 483,291 483,390 ; 483,390 483,435
  BottomLayer - S8 (.GBL) w15: C203.2@563.62,345 v1(599.5,345) 599.5,301.21 C202.1@599.5,293.5 ; v2(1592.48,1161.5) 1595.98,1157.99 C111.2@1617.5,1157.99 ; 1705.01,1172.99 v2(1742.99,1172.99) 1768.01,1172.99 C113.2@1778.5,1162.5
  BottomLayer - S8 (.GBL) w19.68: v1(393,2370) v1(411,2370)
VPLL: C97.1 L6.2 U13.24 | length 995.9
  TopLayer - S1 (.GTL) w8: U13.24@681.61,2139.83 681.61,2147.65 748.65,2147.65 751,2147.65
  TopLayer - S1 (.GTL) w10: v1(1385,1725.5) v1@1385.5,1726
  TopLayer - S1 (.GTL) w15: 685.79,2144 745,2144 748.65,2147.65 754,2153 v1(826,2153)
  TopLayer - S1 (.GTL) w20: L6.2@1385,1687.5 v1(1385,1725.5)
  MidLayer5 - S6 (.G5) w19.68: v1(826,2153) 864.72,2153 1292.22,1725.5 v1(1385,1725.5)
VRTC: C101.1 C146.1 C200.1 U14.1 U15.D7 U16.5 U16.6 U16.8 | length 1060.1
  TopLayer - S1 (.GTL) w6: U16.8@1427.97,1862.97 U16.8@1439.96,1862.97 1462.97,1862.97 1467.5,1867.5 1467.5,1902.5 ; U16.6@1439.96,1902.34 1467.34,1902.34 1467.5,1902.5 ; U16.5@1439.96,1922.03 1462.97,1922.03 1467.5,1917.5 1467.5,1902.5
  TopLayer - S1 (.GTL) w10: v1(1356,1780) 1392,1780 1412,1800 1412,1813.49 C200.1@1407.99,1817.5 1412,1821.51 1412,1847 U16.8@1427.97,1862.97
  TopLayer - S1 (.GTL) w15: v2(1340.51,1318.98) U15.D7@1356.26,1303.25
  MidLayer2 - S3 (.G2) w12: v2(1340.51,1382) 1320,1402.51 1320,1565 1340.51,1585.51 1340.51,1764.51 v1(1356,1780)
  BottomLayer - S8 (.GBL) w12: v2(1340.51,1382) 1362.51,1382 C146.1@1365,1379.51
  BottomLayer - S8 (.GBL) w15: v2(1340.51,1318.98) 1365,1343.46 C146.1@1365,1379.51
  BottomLayer - S8 (.GBL) w15.75: C101.1@1241.97,1691.69 1319.65,1691.69 1356,1728.05 v1(1356,1780)
  BottomLayer - S8 (.GBL) w20: C101.1@1235.47,1697.4 1235.47,1750.91
VTT_DDR: C225.1 C226.1 C227.1 C228.1 C229.1 C230.1 R128.11 R128.12 R128.13 R128.14 R128.15 R128.16 R130.9 R130.10 R130.11 R130.12 R130.13 R130.15 R130.16 R133.9 R133.10 R133.11 R133.12 R133.13 R133.14 R133.15 R133.16 R134.2 U20.3 U20.5 | length 575.1
  MidLayer1 - S2 (.G1) w19.68: v1(372.5,1637.5) v1(372.5,1656)
  MidLayer2 - S3 (.G2) w19.68: v1(372.5,1637.5) v1(372.5,1656)
  MidLayer3 - S4 (.G3) w19.68: v1(372.5,1637.5) v1(372.5,1656)
  MidLayer4 - S5 (.G4) w19.68: v1(372.5,1637.5) v1(372.5,1656)
  MidLayer5 - S6 (.G5) w19.68: v1(372.5,1637.5) v1(372.5,1656)
  MidLayer6 - S7 (.G6) w19.68: v1(372.5,1637.5) v1(372.5,1656)
  BottomLayer - S8 (.GBL) w9.84: U20.3@295,1568.9 U20.3@295,1575.62 295,1603 312.54,1620.54
  BottomLayer - S8 (.GBL) w10: 704.29,1504.92 752.95,1504.92 820,1437.87 R134.2@820,1176.12
  other v1: 660,1555 732.5,1555 757.5,1580 465,1655 520,1655 590,1655 757.5,1655
pads on no net: D8.5 D13.5 FID1.1 FID2.1 FID3.1 FID4.1 FID5.1 FID6.1 H1.1 H2.1 H3.1 H4.1 J4.MH1 J4.MH2 J5.MH1 J5.MH2 J6.10 J6.11 J7.4 J8. J8.6 R20.1 R20.3 R20.8 R20.9 R20.14 R20.16 R69.1 R69.2 R69.15 R69.16 R128.7 R128.8 R128.9 R128.10 R130.3 R130.14 U1.8 U2.4 U5.2 U6.1 U6.7 U6.9 U6.16 U6.25 U6.26 U6.27 U6.28 U6.30 U6.31 U6.32 U6.33 U6.34 U6.39 U6.48 U6.54 U6.55 U6.56 U12.1 U12.7 U12.9 U12.16 U12.22 U12.25 U12.26 U12.27 U12.28 U12.30 U12.31 U12.32 U12.33 U12.34 U12.39 U12.54 U12.55 U12.56 U13.10 U13.11 U13.21 U13.25 U13.31 U13.33 U13.37 U13.38 U13.39 U13.45 U14.3 U14.5 U15.A3 U15.A7 U15.A8 U15.A13 U15.A16 U15.A17 U15.B6 U15.B7 U15.B8 U15.B12 U15.B13 U15.B16 U15.B17 U15.B18 U15.C5 U15.C7 U15.C8 U15.C9 U15.C12 U15.C13 U15.D3 U15.D12 U15.D13 U15.D15 U15.D16 U15.D17 U15.D18 U15.E16 U15.E17 U15.E18 U15.F15 U15.F17 U15.F18 U15.G17 U15.H4 U15.H17 U15.H18 U15.J15 U15.M5 U15.M15 U15.N17 U15.N18 U15.P15 U15.P16 U15.P17 U15.P18 U15.R5 U15.R6 U15.R7 U15.R9 U15.R12 U15.R17 U15.R18 U15.T7 U15.T9 U15.T10 U15.T11 U15.T12 U15.T13 U15.T17 U15.T18 U15.U5 U15.U6 U15.U8 U15.U10 U15.U12 U15.U17 U15.U18 U15.V5 U15.V6 U15.V8 U15.V12 U17.J1 U17.J9 U17.L1 U17.L9 U17.M7 U17.T7 U18.4 U18.9 U19.7 U21.3 U21.5 U22.22 U22.24 U22.27 U22.29 U22.33 U22.34 U22.36 U22.40 U22.41 U22.43 U22.44 U22.45 U22.46 U22.48 U22.52 U22.53 U22.54 U22.55 U22.57 U22.58 U22.60 U24.1 Y4.2 Y4.3

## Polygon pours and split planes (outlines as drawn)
GND on TopLayer - S1 (.GTL) "MidLayer1 - S2 (.G1)-VAUX1" (solid, remove dead copper, pour order 73): 337,1512 313,1488 292,1488 239,1488 230,1497 230,1544 239,1553 313,1553 337,1529 337,1512
NetC5_1 on TopLayer - S1 (.GTL) "MidLayer1 - S2 (.G1)-VAUX1" (solid, remove dead copper, pour order 85): 490,3077.5 490,3140 505,3155 877.5,3155 887.5,3145 887.5,3077.5 847.5,3077.5 825,3055 705,3055 682.5,3077.5
NetC8_1 on TopLayer - S1 (.GTL) "MidLayer1 - S2 (.G1)-VAUX1" (solid, remove dead copper, pour order 82): 567.5,2912.5 567.5,2835 585,2817.5 647.5,2817.5 665,2835 665,2852.99 679.13,2867.13 875.98,2867.13 887.5,2878.64 887.5,2917.5 842.5,2917.5 830,2930 825,2935 797.5,2935 705,2935 700,2930 682.5,2912.5 575,2912.5
GND on TopLayer - S1 (.GTL) "GND" (solid, pour order 125): 2477,2489 2477,2578 2464,2591 2311,2591 2300,2580 2300,2506 2293.97,2499.97 2293.97,2458.66 2319.16,2458.16 2327,2458 2380,2458 2388,2466 2388,2484 2393,2489
NetC17_1 on TopLayer - S1 (.GTL) "Top Layer-No Net 3" (solid, remove dead copper, pour order 124): 2280,2407 2280,2419 2184,2419 2180,2415 2180,2277 2184,2273 2226,2273 2230,2277 2230,2344 2244,2358 2244,2402 2249,2407 2280,2407
GND on TopLayer - S1 (.GTL) "Top Layer-No Net 2" (solid, remove dead copper, pour order 131): 1105,3289.69 1105,3231.61 1119.11,3217.5 1150,3217.5 1350,3217.5 1390,3177.5 1765,3177.5 1765,2971.07 1568.93,2774.82 -210.33,2773.22 1425.2,2775 1425.2,2984.8 1402.5,3007.5 1275,3007.5 1270,3012.5 1270,3072.5 1260,3082.5 1120,3082.5 1105,3097.5 1100,3102.5 1046,3102.5 1031.37,3117.13 991.14,3117.13 982,3126.27 982,3289.09 991.14,3298.23 1096.46,3298.23
NetC1_1 on TopLayer - S1 (.GTL) "Top Layer-No Net 1" (solid, remove dead copper, pour order 129): 1880,3562.5 1880,2967.5 1870,2957.5 1800,2957.5 1790,2967.5 1790,3197.5 1725,3262.5 1725,3562.5 1725,3557.5
NetC4_1 on TopLayer - S1 (.GTL) "Top Layer-No Net" (solid, remove dead copper, pour order 130): 1272.64,3237.2 1272.64,3320.14 1280,3327.5 1315,3327.5 1325,3337.5 1325,3547.5 1340,3562.5 1545,3562.5 1545,3247.5 1530,3232.5 1277.34,3232.5
GND on TopLayer - S1 (.GTL) "Top Layer-GND" (solid, pour order 128): 1389.76,2641.73 1668.27,2641.73 1683.5,2626.5 1683.5,2376.5 1669.21,2362.2 1389.76,2362.2 1374.02,2377.95 1374.02,2625.98
VDDS_DDR on TopLayer - S1 (.GTL) "Top Layer-VDDS_DDR" (solid, remove dead copper, pour order 126): 410.83,1263.32 365.54,1263.32 329.31,1299.55 329.31,1546.69 287.5,1588.5 287.5,1674.5 295.1,1682.1 337.9,1682.1 345,1675 345,1610 377,1578 377,1547 394.81,1529.19 394.81,1350.41 417.1,1350.41 417.1,1269.59
VTT_DDR on TopLayer - S1 (.GTL) "Top Layer-VTT_DDR" (solid, remove dead copper, pour order 127): 369.36,1681.86 775.85,1682.1 788.1,1669.85 788.1,1592.3 766.1,1570.3 766.1,1545.3 762.36,1541.56 653.44,1541.56 645,1550 645,1583.1 618.35,1609.75 448.41,1609.75 440.01,1618.15 369.35,1618.15 362.5,1625 362.5,1675
GND on BottomLayer - S8 (.GBL) "BottomLayer - S8 (.GBL)-GND" (solid, remove dead copper, pour order 117): 2700,1427.5 2700,1925.2 2636.7,1925.2 2584,1872.5 2472,1872.5 2452,1892.5 2235,1892.5 2215,1872.5 2215,1430 2247.34,1397.66 2670.16,1397.66
GND on BottomLayer - S8 (.GBL) "MidLayer1 - S2 (.G1)-VAUX1" (solid, remove dead copper, pour order 92): 1108.27,732.28 1108.27,1435.04 1122.05,1448.82 1161.42,1448.82 1161.42,1431.1 1194.88,1431.1 1309.06,1431.1 1323.82,1445.87 1407.48,1445.87 1416.83,1455.22 1505.91,1455.22 1505.91,1435.04 1728.35,1435.04 1744.09,1419.29 1744.09,723.43 1726.38,723.43 1117.13,723.43
VTT_DDR on BottomLayer - S8 (.GBL) "Layer6 BottomLayer-VTT_DDR" (solid, remove dead copper, pour order 134): 290,1562.99 290,1604.5 352.5,1667 758,1667 767.5,1657.5 767.5,1514.35 753.15,1500 430.7,1500 430.7,1544.3 412.01,1562.99
GND on BottomLayer - S8 (.GBL) "BottomLayer - S8 (.GBL)-GND" (solid, remove dead copper, pour order 116): 2700,330 2700,775 2680,795 2235,795 2215,775 2215,310 2680,310
PHY2_EARTH on BottomLayer - S8 (.GBL) "MidLayer1 - S2 (.G1)-PHY1_EARTH" (solid, remove dead copper, pour order 105): 3515.75,895.67 3938.98,895.67 3980.32,854.33 4496.06,854.33 4496.06,224.41 3505.91,224.41 3454.72,275.59 3454.73,834.65
GND on BottomLayer - S8 (.GBL) "BottomLayer - S8 (.GBL)-GND 1" (solid, remove dead copper, pour order 72): 2731.69,849.8 3315.55,849.8 3358.27,807.09 3358.27,275.59 3307.09,224.41 2759.84,224.41 2673.23,311.02 2673.23,791.34
GND on BottomLayer - S8 (.GBL) "BottomLayer - S8 (.GBL)-No Net" (solid, remove dead copper, pour order 71): 2673.23,1925.2 3305.16,1925.2 3358.27,1872.09 3358.27,1385.83 3313.03,1340.59 2706.65,1340.59 2637.8,1409.45 2637.8,1889.76
PHY1_EARTH on BottomLayer - S8 (.GBL) "MidLayer1 - S2 (.G1)-PHY1_EARTH" (solid, remove dead copper, pour order 104): 3513.78,1996.06 4068.9,1996.06 4145.67,1919.29 4496.06,1919.29 4496.06,1295.28 4198.82,1295.28 4175.2,1271.65 3986.22,1271.65 3940.28,1225.71 3514.45,1225.71 3454.72,1285.43 3454.73,1937.01
VDIG2 on MidLayer5 - S6 (.G5) "MidLayer1 - S2 (.G1)-VAUX1" (solid, remove dead copper, pour order 86): 382.87,2242.13 382.87,2308.07 783.46,2308.07 807.09,2284.45 807.09,2145.67 820.87,2131.89 857.28,2131.89 873.03,2116.14 1366.14,1623.03 1517.72,1623.03 1541.34,1623.03 1631.89,1532.48 1634,1530.37 1634,1471.5 1634,1455.6 1486.12,1455.6 1444.88,1414.37 1370.08,1414.37 661.42,2123.03 651.51,2132.94 641.73,2132.94 554.07,2132.94 503.94,2183.07 441.93,2183.07
VDAC on MidLayer5 - S6 (.G5) "MidLayer1 - S2 (.G1)-VAUX1" (solid, remove dead copper, pour order 93): 1535.43,950.79 1535.43,1083.66 1553.15,1101.38 1567.91,1101.38 1568.9,1100.39 1568.9,1069.88 1586.61,1052.17 1586.61,960.63 1576.77,950.79
VDAC on MidLayer5 - S6 (.G5) "MidLayer1 - S2 (.G1)-VAUX1" (solid, remove dead copper, pour order 88): 1304.13,1061.02 1281.5,1083.66 1281.5,1115.16 1281.5,1232.28 1289.37,1240.16 1292.32,1243.11 1336.61,1243.11 1336.61,1048.23 1333.66,1045.28 1319.88,1045.28 1305.12,1060.04
VDIG2 on MidLayer5 - S6 (.G5) "MidLayer5 - S6 (.G5)-VDIG2" (solid, remove dead copper, pour order 81): 1503.94,937.99 1459.65,937.99 1350.39,1047.24 1350.39,1471.5 1634,1471.5 1634,1173.65 1576.65,1173.65 1519,1116 1519,953.05
GND on MidLayer1 - S2 (.G1) "MidLayer1 - S2 (.G1)-GND" (solid, remove dead copper, pour order 115): 25.59,2891.73 35.43,2901.57 413.39,2901.57 433.07,2921.26 433.07,3704.72 442.91,3714.57 3238.19,3714.57 3248.03,3704.72 3248.03,2035.43 3125.98,1913.39 3125.98,35.43 3116.14,25.59 1181.1,25.59 1181.1,200 819.88,200 819.88,25.59 35.43,25.59 25.59,35.43
VDAC on MidLayer1 - S2 (.G1) "MidLayer1 - S2 (.G1)-VAUX1" (solid, remove dead copper, pour order 96): 1394.68,1262.8 1436.02,1262.8 1473.43,1300.2 1481.3,1308.07 1502.95,1308.07 1521.65,1308.07 1521.65,1266.73 1489.17,1234.25 1456.69,1234.25 1449.8,1234.25 1436.02,1248.03 1394.68,1248.03
VDAC on MidLayer1 - S2 (.G1) "MidLayer1 - S2 (.G1)-VAUX1" (solid, remove dead copper, pour order 97): 1289.37,1074.22 1289.37,1459.65 1289.37,1498.82 1094.49,1693.7 1094.49,1737.4 1121.46,1737.4 1121.46,1703.15 1329.13,1495.47 1329.13,1155.12 1362.2,1122.05 1362.2,1120.08 1329.13,1087.01 1329.13,1059.45 1346.85,1041.73 1334.35,1029.23
GND on MidLayer1 - S2 (.G1) "Signal Layer 1-GND" (solid, remove dead copper, pour order 113): 975,1910 945,1880 295,1880 265,1910 265,2630 295,2660 945,2660 975,2630
GND_OSC0 on MidLayer1 - S2 (.G1) "MidLayer1 - S2 (.G1)-GND_OSC0" (solid, remove dead copper, pour order 99): 1327.76,458.66 1566.93,458.66 1585,476.73 1585,675 1511,749 1511,895 1503,903 1448,903 1437,892 1437,792 1310,665 1310,476.42
GNDA_ADC on MidLayer1 - S2 (.G1) "MidLayer6 - S7 (.G6)-GNDA_ADC" (solid, remove dead copper, pour order 98): 1365,1275 1401,1275 1422,1296 1422,1405 1455,1438 1455,1565 1450,1570 1390,1570 1365,1545
GND on MidLayer1 - S2 (.G1) "MidLayer1 - S2 (.G1)-GND 2" (solid, remove dead copper, pour order 110): 2880,1925 2880,2145 2860,2165 2660,2165 2555,2060 2555,1785 2565,1775 2595,1775 2605,1785 2605,1875 2635,1905 2860,1905
VAUX1 on MidLayer1 - S2 (.G1) "MidLayer1 - S2 (.G1)-VAUX1" (solid, remove dead copper, pour order 100): 1005,808.27 1111.27,808.27 1140,837 1336,1033 1420,1033 1596,1033 1613,1016 1603,1006 1500,1006 1473,979 1440,979 1380,979 1229,828 1162.02,761.02 1005,761.02
VAUX33 on MidLayer1 - S2 (.G1) "MidLayer1 - S2 (.G1)-VAUX33" (solid, remove dead copper, pour order 101): 1005,750.59 1169.59,750.59 1244,825 1389,970 1475,970 1497,992 1506,1001 1539,1001 1539,984 1476,921 1450,921 1420,921 1352,853 1205.5,706.5 1005,706.5
VMMC on MidLayer1 - S2 (.G1) "MidLayer1 - S2 (.G1)-VMMC" (solid, remove dead copper, pour order 102): 1005,694.88 1224.88,694.88 1354,824 1413,824 1416,821 1416,791 1401,776 1279,654 1005,654
GND on MidLayer1 - S2 (.G1) "Signal Layer 1-GND 1" (solid, remove dead copper, pour order 114): 1865,3732.5 1915,3682.5 1915,3607.5 1915,2897.5 1915,2782.5 1865,2732.5 1015,2732.5 965,2782.5 965,3682.5 1015,3732.5
PHY1_EARTH on MidLayer1 - S2 (.G1) "MidLayer1 - S2 (.G1)-PHY1_EARTH" (solid, remove dead copper, pour order 108): 3730,1920 4260,1920 4260,1290 3730,1290 3690,1330 3690,1880
PHY2_EARTH on MidLayer1 - S2 (.G1) "MidLayer1 - S2 (.G1)-PHY1_EARTH" (solid, remove dead copper, pour order 106): 3730,855 4260,855 4260,225 3730,225 3690,265 3690,815
GND on MidLayer1 - S2 (.G1) "MidLayer1 - S2 (.G1)-GND 2" (solid, remove dead copper, pour order 109): 2880,827.5 2880,1032 2844.5,1067.5 2621.63,1067.5 2555,1000.87 2555,687.5 2565,677.5 2595,677.5 2605,687.5 2605,777.5 2635,807.5 2860,807.5
GND on MidLayer1 - S2 (.G1) "GND" (solid, remove dead copper, pour order 112): 2575,2629 2590,2644 2760,2644 2775,2629 2775,2279 2760,2264 2590,2264 2575,2279
GND on MidLayer1 - S2 (.G1) "MidLayer1 - S2 (.G1)-GND 1" (solid, remove dead copper, pour order 111): 2700.79,3606.3 3043.31,3606.3 3062.99,3586.61 3062.99,3421.26 3043.31,3401.57 2704.72,3401.57 2685.04,3421.26 2685.04,3590.55
V5__DC_SITARA on MidLayer4 - S5 (.G4) "MidLayer1 - S2 (.G1)-VAUX1" (solid, remove dead copper, pour order 87): 835.63,2465.55 541.55,2465.55 462,2386 422,2346 422,2120 440.13,2101.87 551.67,2101.87 580.71,2130.91 651.57,2130.91 680.61,2101.87 775.1,2101.87 852.36,2179.13 852.36,2448.82
VAUX2 on MidLayer4 - S5 (.G4) "MidLayer1 - S2 (.G1)-VAUX1" (solid, remove dead copper, pour order 80): 1608.27,1446.85 965.55,2089.57 965.55,2358.27 848.43,2475.39 533.39,2475.39 447.98,2389.98 422.24,2389.95 422.24,2512.8 500,2590.55 904.53,2590.55 1074.8,2420.28 1074.8,2142.72 1621.06,1596.46 1621.06,1459.65
VDD1_SMPS on MidLayer4 - S5 (.G4) "MidLayer1 - S2 (.G1)-VAUX1" (solid, remove dead copper, pour order 78): 837.6,2136.81 837.6,2040.35 1130.91,1747.05 1130.91,1700.32 1423.74,1407.48 1471.62,1407.48 1549.79,1485.64 952.76,2082.68 952.76,2136.81 928.15,2161.42 862.2,2161.42
VDD2_SMPS on MidLayer4 - S5 (.G4) "MidLayer1 - S2 (.G1)-VAUX1" (solid, remove dead copper, pour order 74): 187.01,2627.95 196.85,2637.8 300.2,2637.8 310.04,2627.95 310.04,2139.76 390.75,2059.05 755.91,2059.05 1388.02,1426.94 1326.54,1426.94 1309.06,1409.45 1309.06,1403.54 1301.18,1403.54 1281.5,1423.23 745.08,1959.65 304.13,1959.65 187.01,2076.77
VDD2_SMPS on MidLayer4 - S5 (.G4) "Layer5 PWR-VDD2_SMPS_AM335X" (solid, remove dead copper, pour order 132): 1300,1437.5 1377.46,1437.5 1397.5,1417.46 1397.5,1276.47 1454.49,1219.49 1493.97,1180 1520,1180 1570,1130 1570,1035 1535,1000 1320,1000 1300,1020
VDDS_DDR on MidLayer4 - S5 (.G4) "Layer5 PWR-VDDS_DDR" (solid, remove dead copper, pour order 133): 304.13,1947.83 743.11,1947.84 1285,1405.94 1285,1000 1100,815 325,815 250,890 250,1893.7
VDD1_SMPS on MidLayer4 - S5 (.G4) "MidLayer4 - S5 (.G4)-VDD1_SMPS" (solid, remove dead copper, pour order 118): 1570,1153 1560,1153 1513,1200 1481,1200 1425,1256 1409,1272 1409,1436 1409,1455.17 1356.59,1507.59 1388,1539 1435,1492 1472,1492 1543.43,1492 1555,1480.43 1555,1250 1570,1235
VAUX2 on MidLayer4 - S5 (.G4) "MidLayer4 - S5 (.G4)-VAUX2" (solid, remove dead copper, pour order 122): 1564,1597 1564,1271 1578,1257 1578,1016 1556,994 1554,992 1481,992 1311,992 1206,887 1206,79 1226,59 1713,59 1734,80 1734,430 1679,485 1679,1541.47 1623.47,1597
V11PHY on MidLayer4 - S5 (.G4) "MidLayer4 - S5 (.G4)-V11PHY" (solid, remove dead copper, pour order 67): 2705.02,1470.02 2704.98,1791.02 2631,1865 2290,1865 2265,1840 2265,1455 2290,1430 2665,1430
VMMC on MidLayer4 - S5 (.G4) "MidLayer4 - S5 (.G4)-VMMC" (solid, remove dead copper, pour order 95): 1075,695 325,695 270,640 270,560 270,110 325,55 785,55 820,90 820,305 945,430 1075,560 1075,695
V25PHY on MidLayer4 - S5 (.G4) "MidLayer4 - S5 (.G4)-V25PHY" (solid, remove dead copper, pour order 64): 2847.5,1882 2697,1882 2690.5,1875.5 2690.5,1824.5 2720,1795 2720,1460 2690.5,1430.5 2690.5,1410 2782.05,1410 2847.5,1475.45
V25PHY on MidLayer4 - S5 (.G4) "MidLayer4 - S5 (.G4)-V25PHY" (solid, remove dead copper, pour order 63): 2827.76,1455.71 2723.43,1455.71 2690.5,1422.78 2690.5,1328 2712,1306.5 2712,861.52 2690.5,840.02 2690.5,727 2720,697.5 2720,425 2788.18,425 2827.76,464.57
V11PHY on MidLayer4 - S5 (.G4) "MidLayer4 - S5 (.G4)-V11PHY 2" (solid, remove dead copper, pour order 62): 2675,1815 2675,1938.78 2715,1978.78 2715,2245 2705,2255 2590,2255 2555,2220 2555,1875 2540,1860 2540,1815
V11PHY on MidLayer4 - S5 (.G4) "MidLayer4 - S5 (.G4)-V11PHY" (solid, remove dead copper, pour order 66): 2705.02,372.52 2704.98,693.52 2631,767.5 2290,767.5 2265,742.5 2265,357.5 2290,332.5 2665,332.5
V11PHY on MidLayer4 - S5 (.G4) "MidLayer4 - S5 (.G4)-V11PHY 1" (solid, remove dead copper, pour order 65): 2678,710 2678,845.5 2700,867.5 2700,1258 2678,1280 2678,1460 2480,1460 2480,1430 2520,1430 2550,1400 2550,1290 2550,710
VDDIO on MidLayer4 - S5 (.G4) "MidLayer4 - S5 (.G4)-VDDIO" (solid, remove dead copper, pour order 75): 2091.54,3632.87 3115.16,3632.87 3210,3538.03 3210,3070 3210,2010 3115.16,1915.16 3115.16,75.16 3098.07,58.07 1773.62,58.07 1752.97,78.72 1752.9,447.1 1700,500 1700,1550.98 1102.36,2148.62 1102.36,2425.2 1337.17,2660 1802.72,2660 2000,2857.28 2000,3541.34
V25PHY on MidLayer4 - S5 (.G4) "MidLayer4 - S5 (.G4)-V25PHY 1" (solid, remove dead copper, pour order 61): 2690.5,1858 2690.5,1931.64 2731.3,1972.44 2731.3,2241.14 2731.3,2617.13 2753.94,2639.76 2858.27,2639.76 2874.02,2624.02 2874.02,2186.02 2847.44,2159.45 2847.44,1944.88 2847.44,1858
FT_VDD1V8 on MidLayer2 - S3 (.G2) "MidLayer1 - S2 (.G1)-VAUX1" (solid, remove dead copper, pour order 76): 2381.89,2834.65 2381.89,3208.66 2401.57,3228.35 2807.09,3228.35 2826.77,3208.66 2826.77,2834.65 2807.09,2814.96 2401.57,2814.96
